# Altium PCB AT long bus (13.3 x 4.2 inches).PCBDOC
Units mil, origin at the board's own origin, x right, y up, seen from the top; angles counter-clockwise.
Board outline 13300 x 4200 mil, 10 copper layers (TopLayer, MidLayer1, MidLayer2, MidLayer3, MidLayer4, MidLayer5, MidLayer6, MidLayer7, MidLayer8, BottomLayer); 1 components, 0 nets, 103 pads, 0 vias.
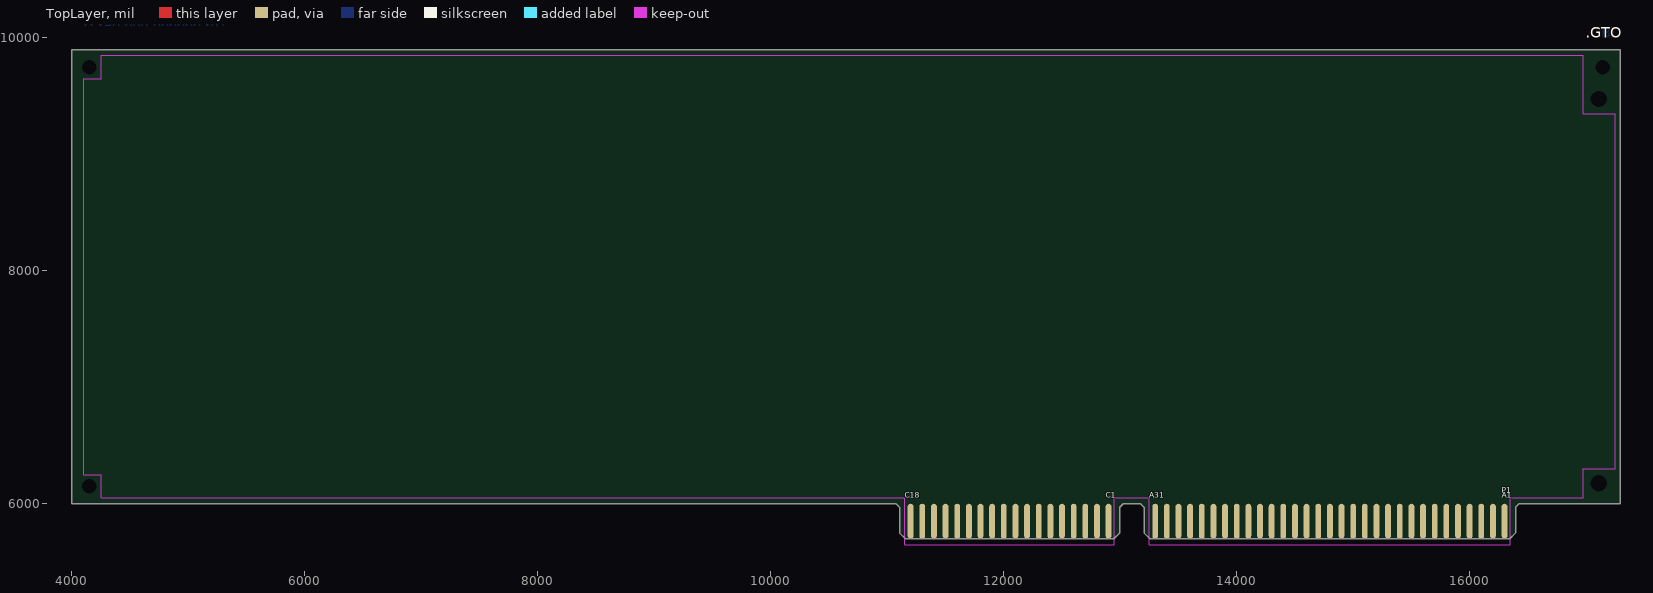
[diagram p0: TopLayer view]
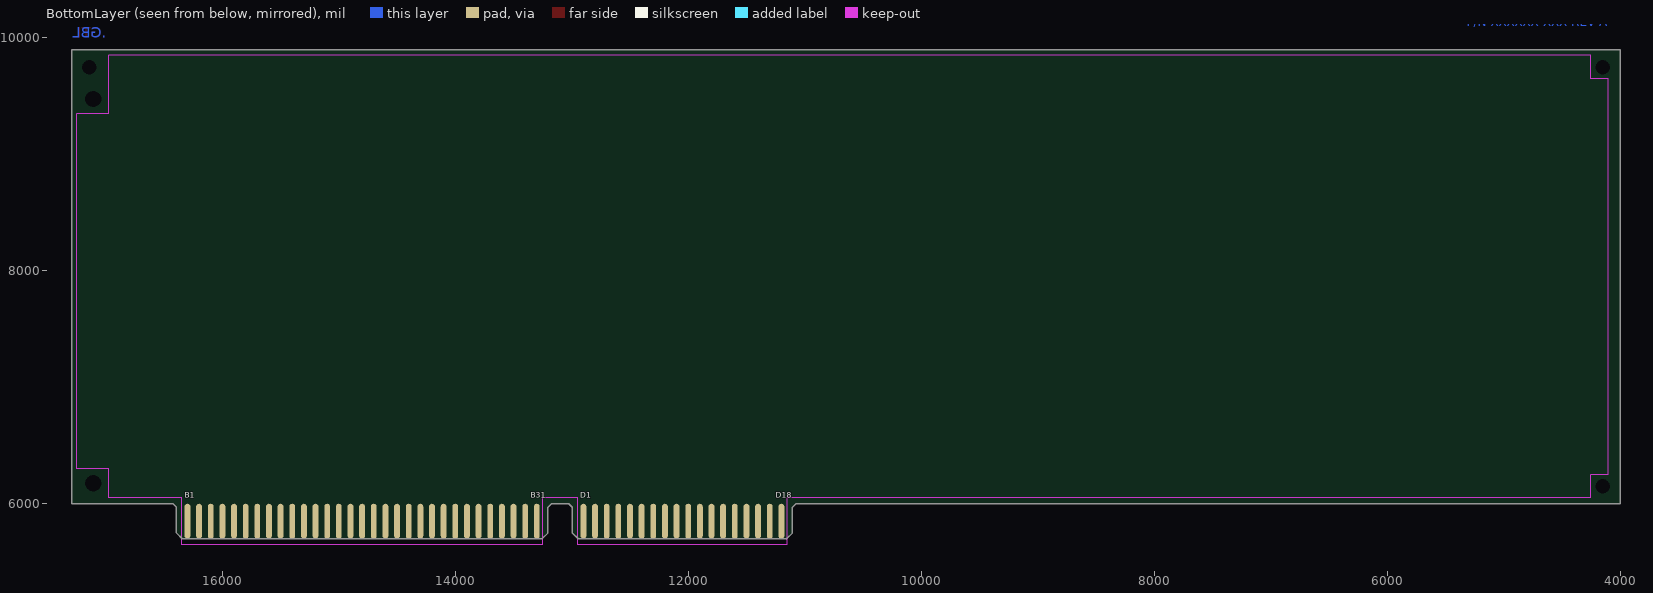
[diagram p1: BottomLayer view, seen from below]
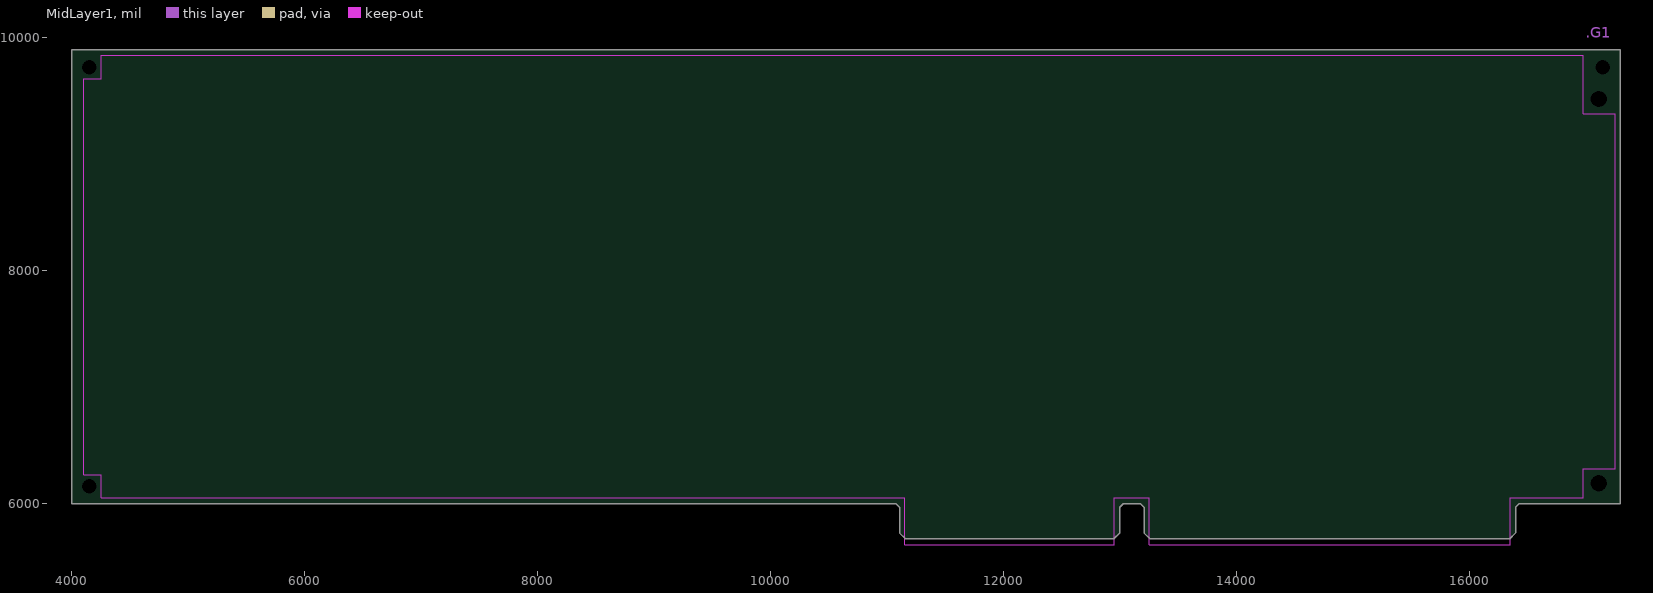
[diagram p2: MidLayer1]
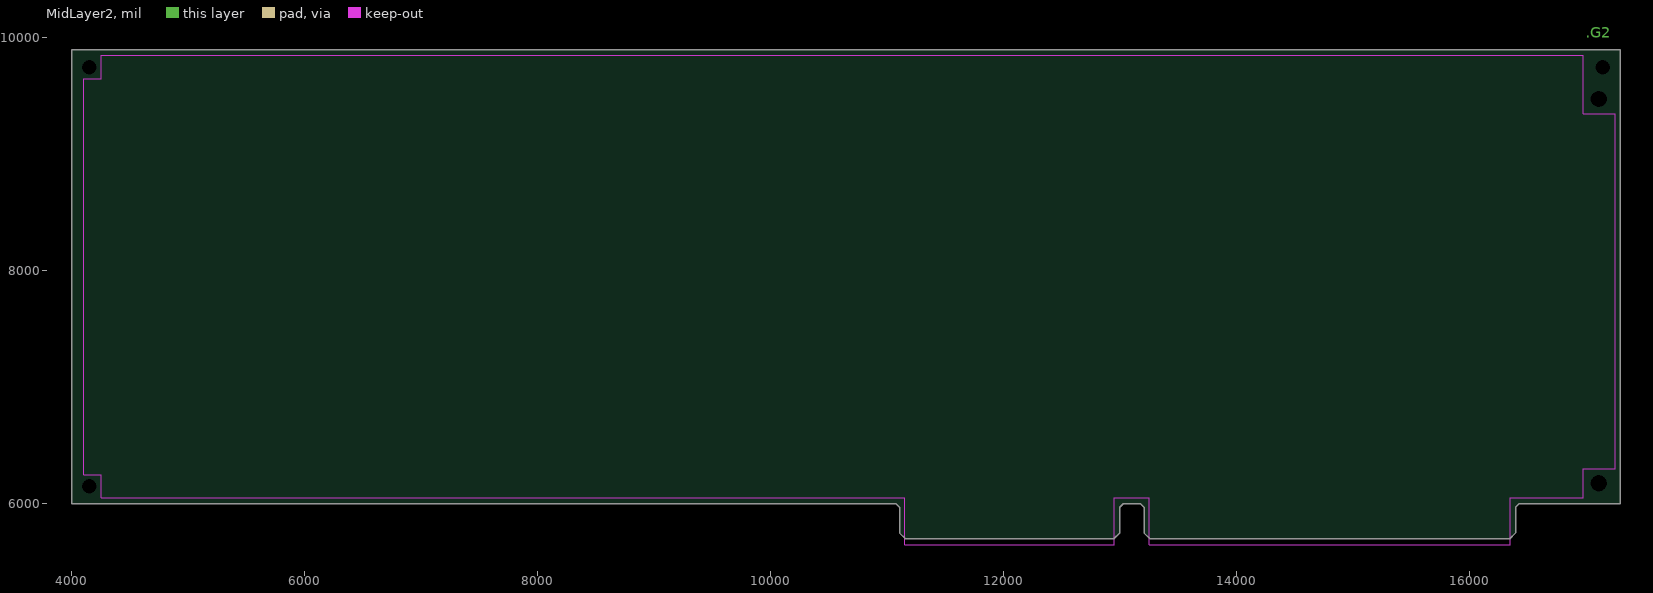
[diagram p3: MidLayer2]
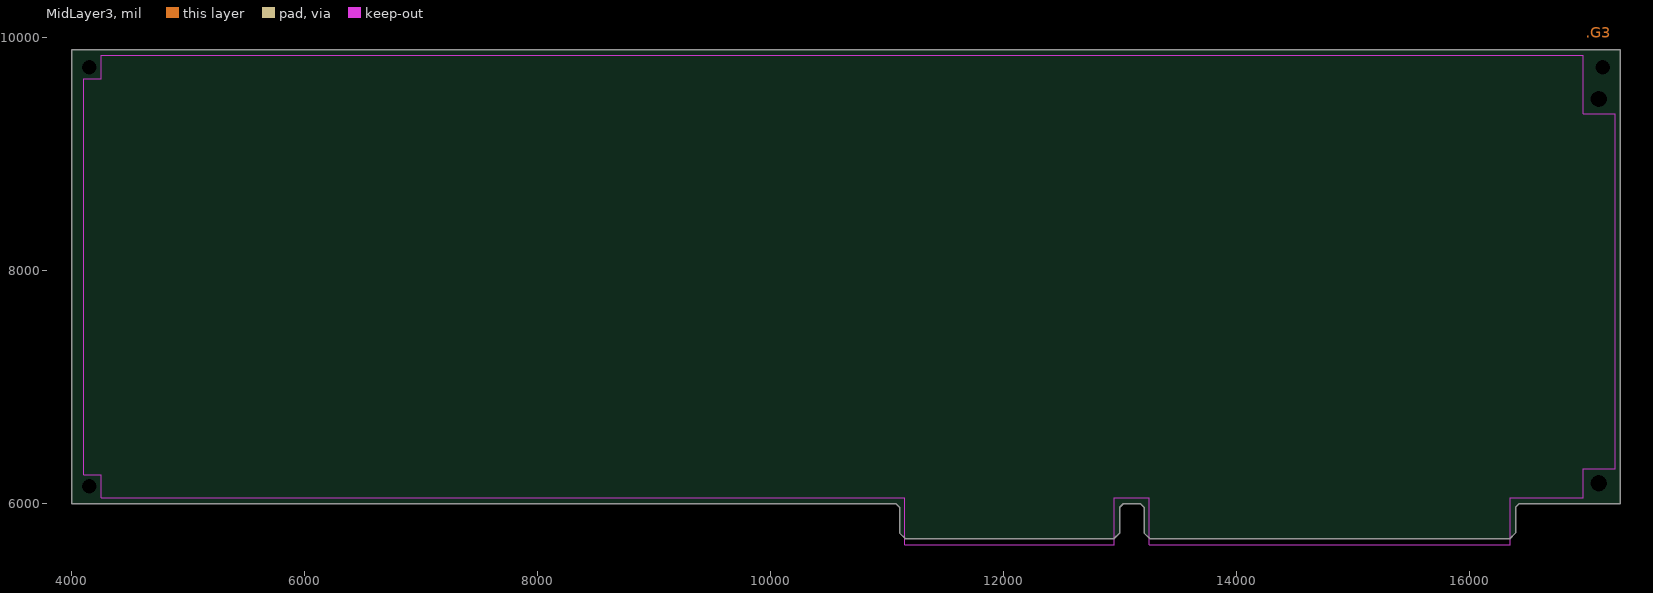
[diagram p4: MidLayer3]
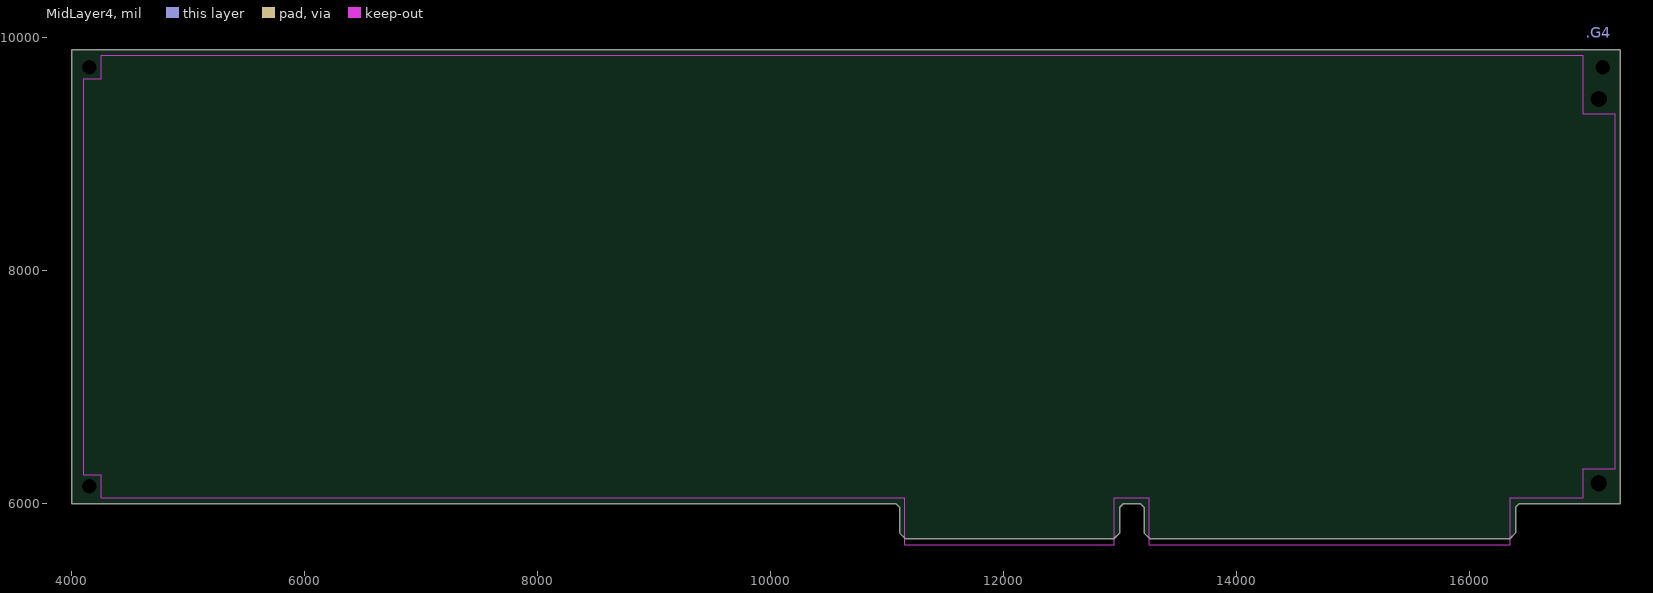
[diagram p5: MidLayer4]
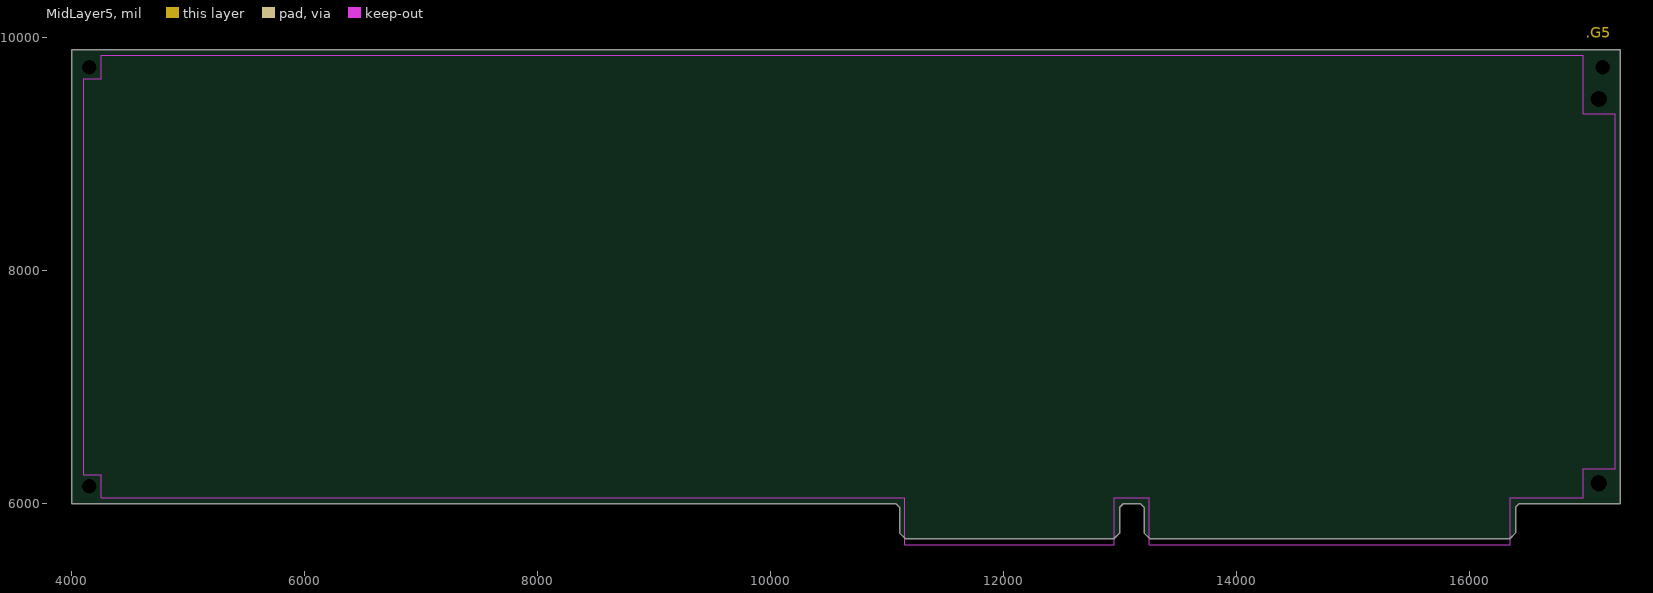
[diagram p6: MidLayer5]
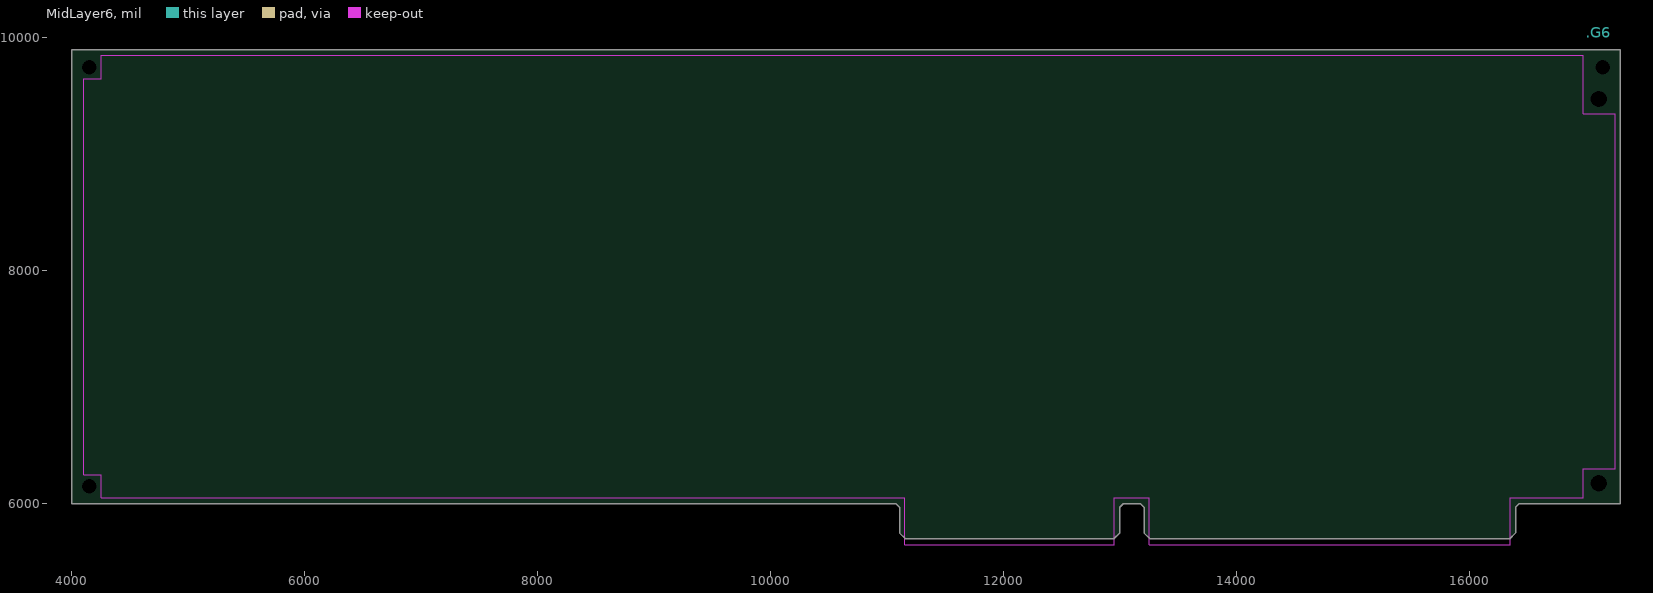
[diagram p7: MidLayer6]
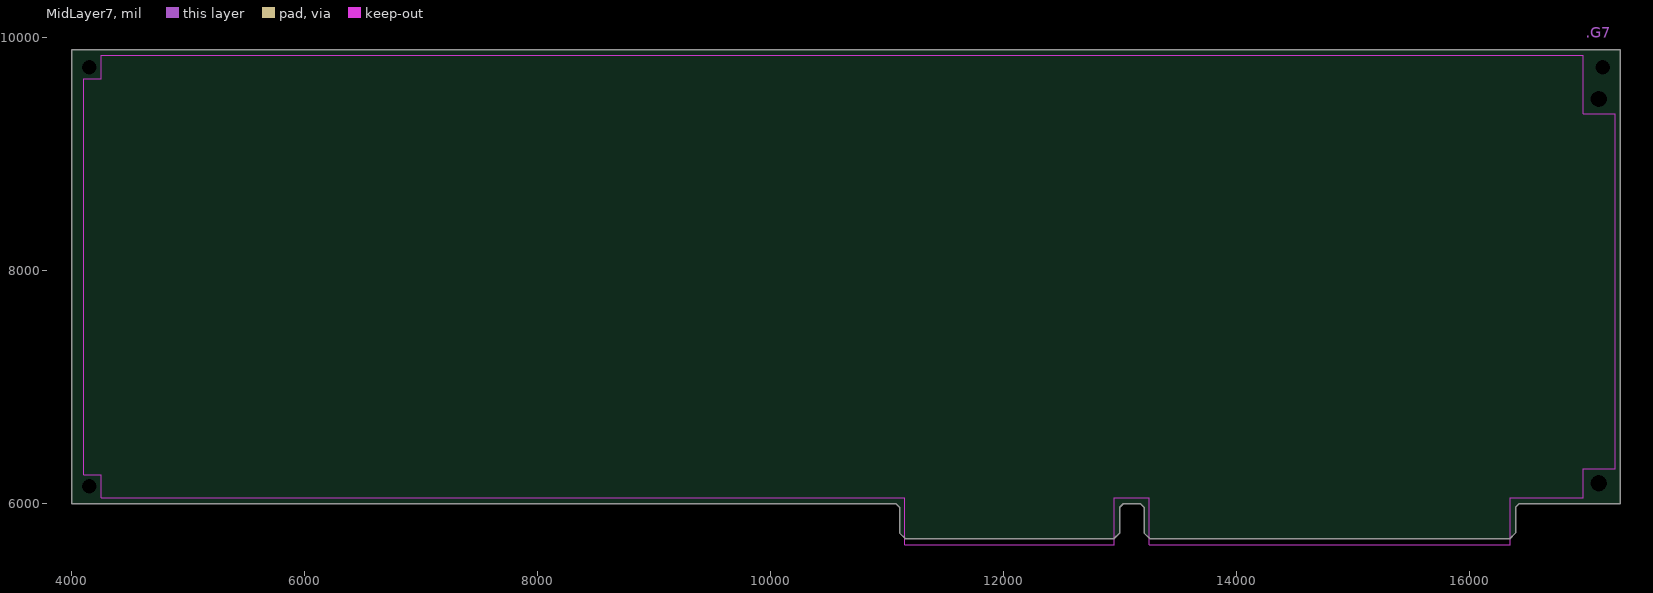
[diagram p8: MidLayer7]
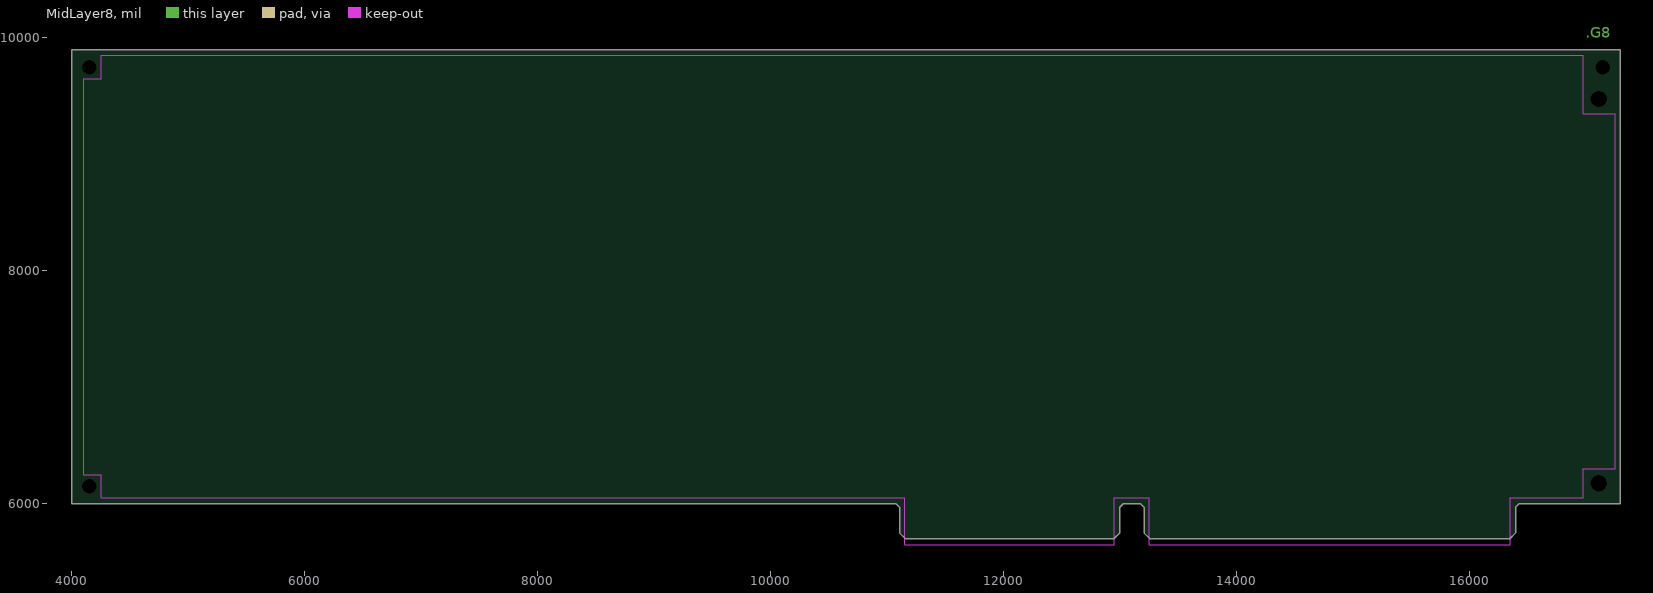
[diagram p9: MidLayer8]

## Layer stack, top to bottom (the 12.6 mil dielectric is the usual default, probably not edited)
TopSolder: solder mask 0.4, Solder Resist, Dk 3.5
TopLayer: signal copper 1.4
Dielectric1: core 12.6, FR-4, Dk 4.8
MidLayer1: signal copper 1.4
Dielectric2: prepreg 12.6, FR-4, Dk 4.8
MidLayer2: signal copper 1.4
Dielectric3: core 12.6, FR-4, Dk 4.8
MidLayer3: signal copper 1.4
Dielectric4: prepreg 12.6, FR-4, Dk 4.8
MidLayer4: signal copper 1.4
Dielectric5: core 12.6, FR-4, Dk 4.8
MidLayer5: signal copper 1.4
Dielectric6: prepreg 12.6, FR-4, Dk 4.8
MidLayer6: signal copper 1.4
Dielectric7: core 12.6, FR-4, Dk 4.8
MidLayer7: signal copper 1.4
Dielectric8: prepreg 12.6, FR-4, Dk 4.8
MidLayer8: signal copper 1.4
Dielectric9: core 12.6, FR-4, Dk 4.8
BottomLayer: signal copper 1.4
BottomSolder: solder mask 0.4, Solder Resist, Dk 3.5

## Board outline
4000,6000 11080,6000 11110,5970 11110,5750 11160,5700 12950,5700 13000,5750 13000,5970 13030,6000 13180,6000 13210,5970 13210,5750 13260,5700 16350,5700 16400,5750 16400,5970 16430,6000 17300,6000 17300,9900 4000,9900

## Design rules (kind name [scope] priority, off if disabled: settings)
Clearance [All] p1: gap=10
FabricationTestPointUsage TestPointUsage [All] p1: valid=0 allowmultiple=FALSE
FabricationTestpoint Testpoint [All] p1: side=3 testpointundercomponent=TRUE minsize=40 maxsize=100 preferedsize=60 minholesize=20 maxholesize=40 preferedholesize=32 testpointgrid=1 allowsidetop=TRUE allowsidebottom=TRUE usegrid=TRUE gridtolerance=0.01
PasteMaskExpansion PasteMaskExpansion_1 [InComponent('P1')] p1: expansion=-150
PasteMaskExpansion [All] p2: expansion=0
PlaneClearance [All] p1: clearance=10
PolygonConnect [All] p1: connectstyle=Relief reliefconductorwidth=10 reliefentries=4 polygonreliefangle="90 Angle" airgapwidth=10
RoutingVias [All] p1: holewidth=28 width=50 viastyle="Through Hole" minholewidth=28 minwidth=50 maxholewidth=28 maxwidth=50
SilkToSolderMaskClearance SilkscreenOverComponentPads [IsPad] p1: minsilkscreentomaskgap=10 clearancetoexposedcopper=TRUE
SolderMaskExpansion [All] p1: expansion=2
Width [All] p1: maxlimit=10 minlimit=10 preferedwidth=10
25 further rules are at their usual default settings.

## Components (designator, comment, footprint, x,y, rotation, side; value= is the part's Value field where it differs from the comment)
P1 "PCATEDGE" PCATEDGE 16305,5850 r0 top locked

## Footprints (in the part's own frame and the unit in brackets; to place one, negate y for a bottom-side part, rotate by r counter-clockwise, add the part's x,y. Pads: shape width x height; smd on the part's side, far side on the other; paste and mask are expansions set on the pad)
PCATEDGE [mil]
  oval 50x300 smd: A1(0,0) A2(-100,0) A3(-200,0) A4(-300,0) A5(-400,0) A6(-500,0) A7(-600,0) A8(-700,0) A9(-800,0) A10(-900,0) A11(-1000,0) A12(-1100,0) A13(-1200,0) A14(-1300,0) A15(-1400,0) A16(-1500,0) A17(-1600,0) A18(-1700,0) A19(-1800,0) A20(-1900,0) A21(-2000,0) A22(-2100,0) A23(-2200,0) A24(-2300,0) A25(-2400,0) A26(-2500,0) A27(-2600,0) A28(-2700,0) A29(-2800,0) A30(-2900,0) A31(-3000,0) C1(-3400,0) C2(-3500,0) C3(-3600,0) C4(-3700,0) C5(-3800,0) C6(-3900,0) C7(-4000,0) C8(-4100,0) C9(-4200,0) C10(-4300,0) C11(-4400,0) C12(-4500,0) C13(-4600,0) C14(-4700,0) C15(-4800,0) C16(-4900,0) C17(-5000,0) C18(-5100,0)
  oval 50x300 smd far side: B1(0,0) B2(-100,0) B3(-200,0) B4(-300,0) B5(-400,0) B6(-500,0) B7(-600,0) B8(-700,0) B9(-800,0) B10(-900,0) B11(-1000,0) B12(-1100,0) B13(-1200,0) B14(-1300,0) B15(-1400,0) B16(-1500,0) B17(-1600,0) B18(-1700,0) B19(-1800,0) B20(-1900,0) B21(-2000,0) B22(-2100,0) B23(-2200,0) B24(-2300,0) B25(-2400,0) B26(-2500,0) B27(-2600,0) B28(-2700,0) B29(-2800,0) B30(-2900,0) B31(-3000,0) D1(-3400,0) D2(-3500,0) D3(-3600,0) D4(-3700,0) D5(-3800,0) D6(-3900,0) D7(-4000,0) D8(-4100,0) D9(-4200,0) D10(-4300,0) D11(-4400,0) D12(-4500,0) D13(-4600,0) D14(-4700,0) D15(-4800,0) D16(-4900,0) D17(-5000,0) D18(-5100,0)

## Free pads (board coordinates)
  round 50 hole 140: 1(17115,6175) 2(17115,9475)
  round 50 hole 125: 3(17150,9750) 4(4150,9750) 5(4150,6150)

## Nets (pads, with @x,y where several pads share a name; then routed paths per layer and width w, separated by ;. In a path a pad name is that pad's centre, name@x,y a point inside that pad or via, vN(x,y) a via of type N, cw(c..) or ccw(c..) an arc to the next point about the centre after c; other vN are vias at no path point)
pads on no net: P1.A1 P1.A2 P1.A3 P1.A4 P1.A5 P1.A6 P1.A7 P1.A8 P1.A9 P1.A10 P1.A11 P1.A12 P1.A13 P1.A14 P1.A15 P1.A16 P1.A17 P1.A18 P1.A19 P1.A20 P1.A21 P1.A22 P1.A23 P1.A24 P1.A25 P1.A26 P1.A27 P1.A28 P1.A29 P1.A30 P1.A31 P1.B1 P1.B2 P1.B3 P1.B4 P1.B5 P1.B6 P1.B7 P1.B8 P1.B9 P1.B10 P1.B11 P1.B12 P1.B13 P1.B14 P1.B15 P1.B16 P1.B17 P1.B18 P1.B19 P1.B20 P1.B21 P1.B22 P1.B23 P1.B24 P1.B25 P1.B26 P1.B27 P1.B28 P1.B29 P1.B30 P1.B31 P1.C1 P1.C2 P1.C3 P1.C4 P1.C5 P1.C6 P1.C7 P1.C8 P1.C9 P1.C10 P1.C11 P1.C12 P1.C13 P1.C14 P1.C15 P1.C16 P1.C17 P1.C18 P1.D1 P1.D2 P1.D3 P1.D4 P1.D5 P1.D6 P1.D7 P1.D8 P1.D9 P1.D10 P1.D11 P1.D12 P1.D13 P1.D14 P1.D15 P1.D16 P1.D17 P1.D18

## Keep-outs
KeepOutLayer:
  lines w8: 4105,6250 4255,6250 4255,6050 11155,6050 11155,5650 12955,5650 12955,6050 13255,6050 13255,5650 16355,5650 16355,6050 16980,6050 16980,6300 17255,6300 17255,9350 16980,9350 16980,9850 4255,9850 4255,9650 4105,9650 4105,6250

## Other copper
TopLayer:
  text ".GTL" at 17000,10000 h90
MidLayer1:
  text ".G1" at 17000,10000 h90
MidLayer2:
  text ".G2" at 17000,10000 h90
MidLayer3:
  text ".G3" at 17000,10000 h90
MidLayer4:
  text ".G4" at 17000,10000 h90
MidLayer5:
  text ".G5" at 17000,10000 h90
MidLayer6:
  text ".G6" at 17000,10000 h90
MidLayer7:
  text ".G7" at 17000,10000 h90
MidLayer8:
  text ".G8" at 17000,10000 h90
BottomLayer:
  text "P/N XXXXXX-XXX REV A" at 5320,10100 h75
  text ".GBL" at 17000,10000 h90

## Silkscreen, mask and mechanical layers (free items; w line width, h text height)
TopOverlay:
  rectangle: 4281,10303 5031,10503
  rectangle: 4281,10593 5031,10793
  lines w10: 5392.59,10695.97 ccw(c5441,10735.5) 5392.71,10695.83
  text "C" at 5496,10698 h60
  text "2002 COMPANY NAME" at 5646,10698 h75
  text "S/N" at 4031,10650.5 h75
  text "BOARD NAME" at 5496,10523 h75
  text "ASSY NO.: XXXXXX" at 5496,10373 h75
  text "REV" at 4031,10353 h75
  text ".GTO" at 17000,10000 h90
TopPaste:
  text ".GTP" at 17000,10000 h90
BottomPaste:
  text ".GBP" at 17000,10000 h90
TopSolder:
  text ".GTS" at 17000,10000 h90
BottomSolder:
  text ".GBS" at 17000,10000 h90
Mechanical1:
  the board outline again, w20
Mechanical3:
  lines w10: 16990,6125 16990,6075 17040,6075 ; 16990,6150 16990,6200 ; 16990,6225 16990,6275 17040,6275 ; 16990,9425 16990,9375 17040,9375 ; 16990,9450 16990,9500 ; 16990,9525 16990,9575 17040,9575 ; 17065,6075 17115,6075 ; 17065,6275 17115,6275 ; 17065,9375 17115,9375 ; 17065,9575 17115,9575 ; 17140,6075 17190,6075 ; 17140,6275 17190,6275 ; 17140,9375 17190,9375 ; 17140,9575 17190,9575 ; 17215,6075 17265,6075 ; 17215,6275 17265,6275 ; 17215,9375 17265,9375 ; 17215,9575 17265,9575 ; 17300,6075 17340,6075 17340,4925 17365,4925 17365,9650 17790,9650 17790,9675 17340,9675 17340,9575 17300,9575 ; 17300,6275 17340,6275 17340,9375 17300,9375
Mechanical4:
  circle w10: c11145.67,5719.32 r100
  lines w10: 18405,7800 18480,7725 18555,7800 18630,7725 18705,7800 18780,7725 18855,7800 ; 18886.25,6718.75 19130,6475 19330,6475 ; 20030,7925 20755,7925 ; 21380,6475 21130,6475 21423.75,6768.75 ; 22330,6675 22330,7075 22530,7175 22130,7275 22330,7375 22330,7775 ; 11003.67,5666.32 11003.67,5721.32 11023.67,5671.32 11003.67,5666.32 ; 11003.87,5721.16 11005,5775 11025.36,5771.79 11003.87,5721.16 ; 18780,6825 18905,6737.5 18867.5,6700 18780,6825 ; 21405,6787.5 21530,6875 21442.5,6750 21405,6787.5
  lines w20: 18430,7775 18430,6875 18530,6775 18730,6775 18830,6875 18830,7775 ; 21430,7775 21430,6975 21630,6775 22330,6775
  text ".Pcb_File_Name_No_Path" at 15100,10190 h90
  text ".Printout_Name" at 15100,10000 h90
  text "DETAIL A" at 20030,7975 h120
  text "o" at 20055,6500 h60
  text "o" at 22105,6500 h60
  text ".020 X 45  CHAMFER" at 19405,6425 h90
  text "0.05 X 45  CHAMFER" at 21455,6425 h90
  text "BOTH SIDES" at 19405,6250 h90
  text "TYP 4 PLCS" at 21455,6250 h90
  text "ENTIRE LENGTH OF" at 19405,6075 h90
  text "EDGE CONNECTOR" at 19405,5900 h90
  text "SEE DETAIL A" at 10230,5675 h75
DrillDrawing:
  text ".LEGEND" at 18335,8655 h90
  text "Drilling Details." at 18340,8485 h90

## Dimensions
16350,5700 to 16430,6000 on Mechanical4
4150,5980 to 4000,6000 on Mechanical4
3980,6150 to 4000,6000 on Mechanical4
